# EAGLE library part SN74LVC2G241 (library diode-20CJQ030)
Ti's SN74LVC2G241 Dual Buffer/Driver with 3.States Output Description: This dual buffer/line driver is designed for 1.65-V to 5.5-V VCC operation. The SN74LVC2G241 is designed specifically to improve both the performance and memory-address drivers, clock drivers, and bus-oriented receivers and transmitters. Features: Available in the Texas Instruments NanoStar and NanoFree Packages Supports 5-V VCC Operation Inputs Accept Voltages to 5.5 V Max tpd of 4.1 ns at 3.3 V Low Power Consumption, 10-uA Max ICC ±24-mA Output Drive at 3.3 V Typical VOLP (Output Ground Bounce) less then 0.8 V at VCC = 3.3 V, TA = 25°C Typical VOHV (Output VOH Undershoot) greater then 2 V at VCC = 3.3 V, TA = 25°C Ioff Supports Partial-Power-Down Mode Operation Latch-Up Performance Exceeds 100 mA Per JESD 78, Class II ESD Protection Exceeds JESD 22 - 2000-V Human-Body Model (A114-A) - 200-V Machine Model (A115-A) - 1000-V Charged-Device Model (C101) Please send any comments to: messi@users.sourceforge.net
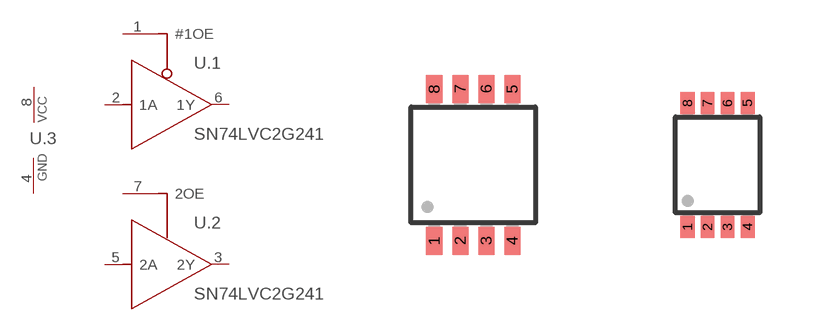
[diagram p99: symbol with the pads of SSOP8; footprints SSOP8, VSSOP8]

Designator prefix U; gates .1=INV_BUFFER .2=NON_INV_BUFFER .3=PWR_GND

## SN74LVC2G241DCT  [SSOP8]
1  .1:#1OE  in
2  .1:1A  in
3  .2:2Y  out
4  .3:GND  pwr
5  .2:2A  in
6  .1:1Y  out
7  .2:2OE  in
8  .3:VCC  pwr

## SN74LVC2G241DCU  [VSSOP8]
Pads as for SSOP8

## Footprint SSOP8 (pad centres in mm)
smd 0.4 x 0.7: 1 -0.975,-1.9; 2 -0.325,-1.9; 3 0.325,-1.9; 4 0.975,-1.9; 5 0.975,1.9; 6 0.325,1.9; 7 -0.325,1.9; 8 -0.975,1.9

## Footprint VSSOP8 (pad centres in mm)
smd 0.35 x 0.55: 1 -0.75,-1.55; 2 -0.25,-1.55; 3 0.25,-1.55; 4 0.75,-1.55; 5 0.75,1.55; 6 0.25,1.55; 7 -0.25,1.55; 8 -0.75,1.55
